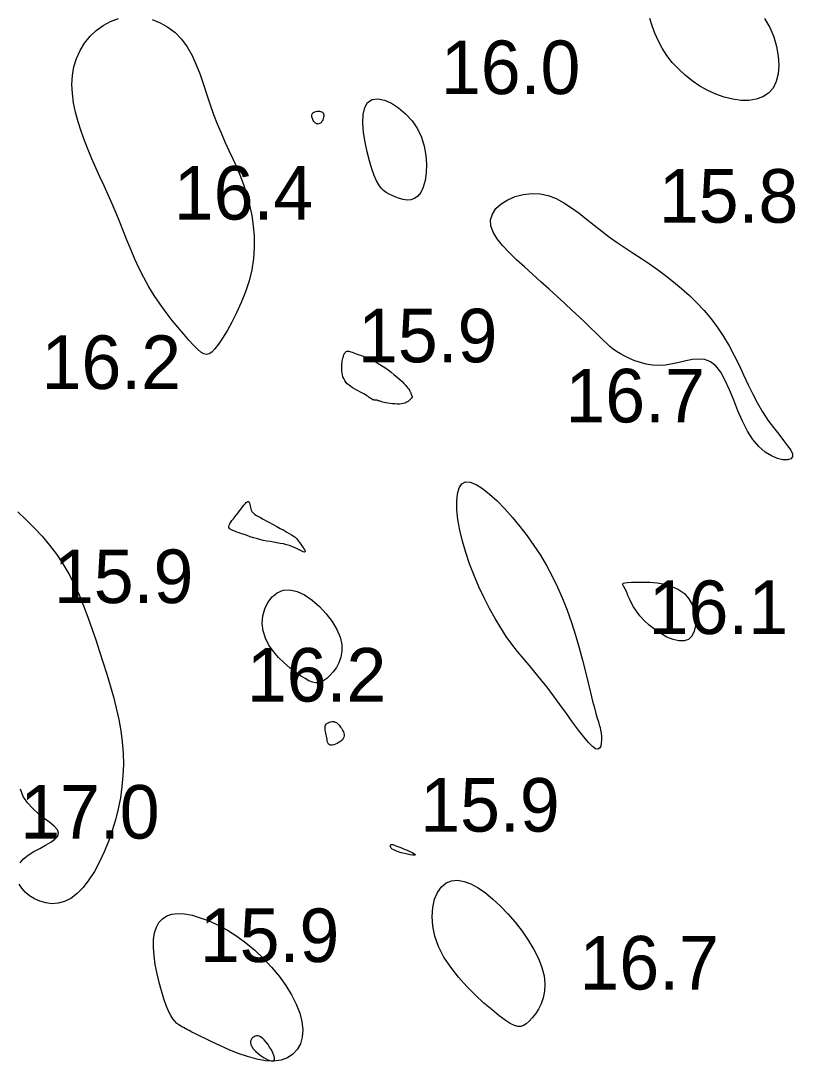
# Model space of a CAD drawing. Extents: x 3040093 to 3056816, y 408076 to 509144.
# Drawn here: x 3045686.6 to 3045758.8, y 434161.7 to 434258.8 of the extents above; entities that cross this region are included whole.
import ezdxf

# ---------------------------------------------------------------- set-up
doc = ezdxf.new("R2010")
doc.units = 0
doc.layers.add('V-CHAN-CONT-EL17', color=7, linetype='Continuous')
doc.layers.add('V-TOPO-SOUN-0610', color=7, linetype='Continuous')

msp = doc.modelspace()

# ---------------------------------------------------------------- linework, layer by layer
at = {"layer": 'V-CHAN-CONT-EL17'}
for points in [[(3045698.81, 434258.889), (3045699.574, 434258.588), (3045700.298, 434258.179), (3045700.969, 434257.665), (3045701.571, 434257.048), (3045702.094, 434256.332), (3045702.547, 434255.534), (3045702.944, 434254.671), (3045703.298, 434253.762), (3045703.622, 434252.824), (3045703.93, 434251.876), (3045704.236, 434250.936), (3045704.553, 434250.021), (3045704.891, 434249.146), (3045705.247, 434248.304), (3045705.614, 434247.486), (3045705.985, 434246.682), (3045706.354, 434245.879), (3045706.713, 434245.07), (3045707.055, 434244.242), (3045707.374, 434243.387), (3045707.662, 434242.495), (3045707.912, 434241.57), (3045708.115, 434240.614), (3045708.262, 434239.633), (3045708.344, 434238.631), (3045708.354, 434237.611), (3045708.282, 434236.579), (3045708.12, 434235.539), (3045707.865, 434234.497), (3045707.531, 434233.469), (3045707.139, 434232.472), (3045706.708, 434231.525), (3045706.259, 434230.646), (3045705.811, 434229.851), (3045705.385, 434229.16), (3045705, 434228.59), (3045704.671, 434228.155), (3045704.387, 434227.853), (3045704.13, 434227.678), (3045703.886, 434227.624), (3045703.636, 434227.686), (3045703.365, 434227.858), (3045703.055, 434228.133), (3045702.691, 434228.506), (3045702.26, 434228.97), (3045701.772, 434229.517), (3045701.243, 434230.135), (3045700.688, 434230.816), (3045700.121, 434231.549), (3045699.558, 434232.323), (3045699.013, 434233.13), (3045698.502, 434233.959), (3045698.037, 434234.802), (3045697.611, 434235.654), (3045697.219, 434236.513), (3045696.85, 434237.377), (3045696.498, 434238.242), (3045696.155, 434239.107), (3045695.811, 434239.97), (3045695.459, 434240.826), (3045695.094, 434241.675), (3045694.717, 434242.519), (3045694.334, 434243.36), (3045693.95, 434244.2), (3045693.57, 434245.042), (3045693.199, 434245.888), (3045692.841, 434246.741), (3045692.502, 434247.604), (3045692.188, 434248.477), (3045691.907, 434249.356), (3045691.671, 434250.238), (3045691.489, 434251.115), (3045691.372, 434251.984), (3045691.33, 434252.839), (3045691.373, 434253.674), (3045691.512, 434254.486), (3045691.753, 434255.267), (3045692.091, 434256.007), (3045692.517, 434256.696), (3045693.023, 434257.322), (3045693.6, 434257.875), (3045694.238, 434258.343), (3045694.929, 434258.714), (3045695.665, 434258.979)], [(3045755.981, 434258.975), (3045756.455, 434258.147), (3045756.829, 434257.27), (3045757.099, 434256.371), (3045757.261, 434255.478), (3045757.313, 434254.615), (3045757.251, 434253.812), (3045757.071, 434253.093), (3045756.771, 434252.486), (3045756.349, 434252.012), (3045755.821, 434251.669), (3045755.205, 434251.448), (3045754.519, 434251.343), (3045753.78, 434251.344), (3045753.008, 434251.445), (3045752.22, 434251.636), (3045751.435, 434251.911), (3045750.668, 434252.261), (3045749.927, 434252.68), (3045749.22, 434253.16), (3045748.553, 434253.693), (3045747.932, 434254.274), (3045747.364, 434254.894), (3045746.856, 434255.547), (3045746.413, 434256.225), (3045746.039, 434256.92), (3045745.731, 434257.619), (3045745.48, 434258.308), (3045745.279, 434258.972)], [(3045686.295, 434212.938), (3045687.065, 434212.209), (3045687.816, 434211.453), (3045688.543, 434210.667), (3045689.237, 434209.849), (3045689.889, 434208.994), (3045690.493, 434208.101), (3045691.044, 434207.167), (3045691.544, 434206.196), (3045692.003, 434205.195), (3045692.426, 434204.168), (3045692.82, 434203.122), (3045693.192, 434202.063), (3045693.55, 434200.996), (3045693.899, 434199.927), (3045694.246, 434198.86), (3045694.584, 434197.797), (3045694.906, 434196.737), (3045695.206, 434195.68), (3045695.476, 434194.626), (3045695.709, 434193.573), (3045695.897, 434192.523), (3045696.033, 434191.475), (3045696.112, 434190.428), (3045696.133, 434189.383), (3045696.097, 434188.342), (3045696.005, 434187.303), (3045695.859, 434186.269), (3045695.659, 434185.24), (3045695.407, 434184.217), (3045695.104, 434183.199), (3045694.751, 434182.192), (3045694.353, 434181.21), (3045693.913, 434180.272), (3045693.436, 434179.396), (3045692.927, 434178.599), (3045692.389, 434177.902), (3045691.828, 434177.32), (3045691.247, 434176.874), (3045690.653, 434176.576), (3045690.054, 434176.415), (3045689.461, 434176.376), (3045688.886, 434176.443), (3045688.339, 434176.6), (3045687.831, 434176.832), (3045687.373, 434177.123), (3045686.975, 434177.457), (3045686.647, 434177.821), (3045686.396, 434178.205)], [(3045686.496, 434180.203), (3045686.826, 434180.572), (3045687.265, 434180.915), (3045687.78, 434181.238), (3045688.327, 434181.543), (3045688.866, 434181.837), (3045689.354, 434182.122), (3045689.749, 434182.406), (3045690.009, 434182.69), (3045690.093, 434182.982), (3045689.973, 434183.285), (3045689.68, 434183.608), (3045689.258, 434183.957), (3045688.752, 434184.342), (3045688.208, 434184.771), (3045687.67, 434185.25), (3045687.183, 434185.789), (3045686.792, 434186.395), (3045686.53, 434187.074)]]:
    msp.add_lwpolyline(points, dxfattribs=at)
for points in [[(3045719.343, 434251.423), (3045719.876, 434251.485), (3045720.491, 434251.363), (3045721.153, 434251.078), (3045721.828, 434250.649), (3045722.48, 434250.096), (3045723.073, 434249.439), (3045723.574, 434248.7), (3045723.954, 434247.897), (3045724.215, 434247.058), (3045724.369, 434246.209), (3045724.426, 434245.377), (3045724.396, 434244.589), (3045724.29, 434243.871), (3045724.117, 434243.25), (3045723.888, 434242.753), (3045723.614, 434242.399), (3045723.303, 434242.176), (3045722.967, 434242.063), (3045722.614, 434242.041), (3045722.254, 434242.09), (3045721.896, 434242.19), (3045721.551, 434242.321), (3045721.228, 434242.462), (3045720.934, 434242.601), (3045720.666, 434242.75), (3045720.419, 434242.928), (3045720.189, 434243.155), (3045719.968, 434243.451), (3045719.753, 434243.834), (3045719.538, 434244.325), (3045719.318, 434244.942), (3045719.092, 434245.693), (3045718.875, 434246.545), (3045718.689, 434247.45), (3045718.554, 434248.361), (3045718.49, 434249.234), (3045718.517, 434250.022), (3045718.656, 434250.678), (3045718.928, 434251.157)], [(3045713.713, 434249.89), (3045713.717, 434249.965), (3045713.734, 434250.034), (3045713.763, 434250.098), (3045713.805, 434250.155), (3045713.86, 434250.205), (3045713.928, 434250.249), (3045714.01, 434250.285), (3045714.106, 434250.313), (3045714.21, 434250.332), (3045714.32, 434250.34), (3045714.429, 434250.337), (3045714.533, 434250.319), (3045714.629, 434250.287), (3045714.71, 434250.239), (3045714.772, 434250.173), (3045714.813, 434250.089), (3045714.832, 434249.99), (3045714.833, 434249.881), (3045714.818, 434249.767), (3045714.789, 434249.652), (3045714.748, 434249.54), (3045714.699, 434249.436), (3045714.643, 434249.346), (3045714.582, 434249.271), (3045714.518, 434249.213), (3045714.452, 434249.172), (3045714.383, 434249.147), (3045714.313, 434249.138), (3045714.242, 434249.144), (3045714.172, 434249.166), (3045714.103, 434249.202), (3045714.036, 434249.252), (3045713.972, 434249.315), (3045713.912, 434249.387), (3045713.858, 434249.467), (3045713.81, 434249.551), (3045713.771, 434249.638), (3045713.741, 434249.725), (3045713.721, 434249.81)], [(3045733.557, 434235.801), (3045732.818, 434236.477), (3045732.134, 434237.14), (3045731.529, 434237.788), (3045731.029, 434238.42), (3045730.659, 434239.033), (3045730.444, 434239.625), (3045730.41, 434240.195), (3045730.573, 434240.738), (3045730.912, 434241.242), (3045731.399, 434241.692), (3045732.003, 434242.074), (3045732.697, 434242.373), (3045733.451, 434242.575), (3045734.235, 434242.666), (3045735.021, 434242.631), (3045735.784, 434242.462), (3045736.525, 434242.173), (3045737.248, 434241.786), (3045737.959, 434241.323), (3045738.662, 434240.804), (3045739.363, 434240.25), (3045740.067, 434239.684), (3045740.778, 434239.126), (3045741.501, 434238.593), (3045742.235, 434238.081), (3045742.977, 434237.582), (3045743.726, 434237.089), (3045744.479, 434236.593), (3045745.235, 434236.086), (3045745.99, 434235.561), (3045746.744, 434235.008), (3045747.493, 434234.422), (3045748.233, 434233.801), (3045748.957, 434233.144), (3045749.66, 434232.451), (3045750.337, 434231.723), (3045750.981, 434230.958), (3045751.587, 434230.156), (3045752.149, 434229.318), (3045752.665, 434228.445), (3045753.143, 434227.546), (3045753.592, 434226.633), (3045754.025, 434225.718), (3045754.45, 434224.812), (3045754.881, 434223.927), (3045755.326, 434223.074), (3045755.796, 434222.266), (3045756.297, 434221.512), (3045756.808, 434220.817), (3045757.302, 434220.185), (3045757.752, 434219.618), (3045758.131, 434219.121), (3045758.414, 434218.696), (3045758.573, 434218.347), (3045758.582, 434218.078), (3045758.423, 434217.892), (3045758.118, 434217.798), (3045757.695, 434217.805), (3045757.185, 434217.923), (3045756.618, 434218.161), (3045756.024, 434218.529), (3045755.433, 434219.034), (3045754.874, 434219.688), (3045754.371, 434220.489), (3045753.917, 434221.401), (3045753.498, 434222.376), (3045753.1, 434223.367), (3045752.709, 434224.328), (3045752.312, 434225.212), (3045751.894, 434225.971), (3045751.443, 434226.56), (3045750.946, 434226.945), (3045750.41, 434227.149), (3045749.839, 434227.209), (3045749.243, 434227.162), (3045748.628, 434227.045), (3045748.001, 434226.895), (3045747.37, 434226.749), (3045746.743, 434226.644), (3045746.125, 434226.609), (3045745.523, 434226.642), (3045744.942, 434226.732), (3045744.386, 434226.87), (3045743.861, 434227.044), (3045743.372, 434227.245), (3045742.925, 434227.463), (3045742.523, 434227.687), (3045742.169, 434227.91), (3045741.85, 434228.138), (3045741.55, 434228.379), (3045741.253, 434228.642), (3045740.943, 434228.935), (3045740.604, 434229.268), (3045740.22, 434229.648), (3045739.775, 434230.084), (3045739.257, 434230.583), (3045738.673, 434231.137), (3045738.031, 434231.737), (3045737.343, 434232.375), (3045736.618, 434233.041), (3045735.866, 434233.725), (3045735.098, 434234.419), (3045734.324, 434235.114)], [(3045719.723, 434223.374), (3045719.677, 434223.377), (3045719.63, 434223.377), (3045719.583, 434223.378), (3045719.535, 434223.382), (3045719.484, 434223.39), (3045719.43, 434223.405), (3045719.373, 434223.43), (3045719.312, 434223.465), (3045719.245, 434223.511), (3045719.169, 434223.566), (3045719.082, 434223.63), (3045718.981, 434223.703), (3045718.864, 434223.782), (3045718.729, 434223.868), (3045718.573, 434223.959), (3045718.396, 434224.055), (3045718.201, 434224.157), (3045717.996, 434224.264), (3045717.787, 434224.377), (3045717.58, 434224.497), (3045717.382, 434224.625), (3045717.198, 434224.76), (3045717.036, 434224.904), (3045716.9, 434225.056), (3045716.789, 434225.215), (3045716.7, 434225.38), (3045716.632, 434225.549), (3045716.582, 434225.72), (3045716.548, 434225.892), (3045716.526, 434226.062), (3045716.516, 434226.229), (3045716.514, 434226.393), (3045716.519, 434226.551), (3045716.53, 434226.704), (3045716.547, 434226.851), (3045716.569, 434226.992), (3045716.594, 434227.126), (3045716.622, 434227.253), (3045716.652, 434227.372), (3045716.683, 434227.483), (3045716.715, 434227.586), (3045716.751, 434227.678), (3045716.79, 434227.758), (3045716.835, 434227.826), (3045716.885, 434227.881), (3045716.942, 434227.92), (3045717.007, 434227.944), (3045717.081, 434227.951), (3045717.166, 434227.942), (3045717.261, 434227.92), (3045717.37, 434227.886), (3045717.493, 434227.842), (3045717.631, 434227.789), (3045717.786, 434227.729), (3045717.959, 434227.664), (3045718.15, 434227.595), (3045718.36, 434227.521), (3045718.586, 434227.437), (3045718.828, 434227.343), (3045719.084, 434227.235), (3045719.354, 434227.111), (3045719.636, 434226.968), (3045719.928, 434226.804), (3045720.229, 434226.617), (3045720.535, 434226.413), (3045720.839, 434226.195), (3045721.136, 434225.97), (3045721.42, 434225.744), (3045721.687, 434225.521), (3045721.93, 434225.308), (3045722.143, 434225.109), (3045722.324, 434224.93), (3045722.474, 434224.769), (3045722.596, 434224.627), (3045722.693, 434224.502), (3045722.77, 434224.393), (3045722.828, 434224.3), (3045722.873, 434224.22), (3045722.906, 434224.153), (3045722.932, 434224.099), (3045722.952, 434224.054), (3045722.966, 434224.018), (3045722.977, 434223.988), (3045722.986, 434223.962), (3045722.993, 434223.939), (3045723, 434223.917), (3045723.009, 434223.893), (3045723.02, 434223.868), (3045723.033, 434223.839), (3045723.047, 434223.809), (3045723.06, 434223.779), (3045723.072, 434223.748), (3045723.082, 434223.718), (3045723.088, 434223.689), (3045723.09, 434223.663), (3045723.087, 434223.638), (3045723.078, 434223.616), (3045723.063, 434223.593), (3045723.043, 434223.568), (3045723.016, 434223.541), (3045722.984, 434223.51), (3045722.944, 434223.472), (3045722.898, 434223.428), (3045722.845, 434223.376), (3045722.783, 434223.318), (3045722.709, 434223.258), (3045722.622, 434223.197), (3045722.519, 434223.14), (3045722.398, 434223.09), (3045722.257, 434223.048), (3045722.093, 434223.019), (3045721.906, 434223.004), (3045721.701, 434223.003), (3045721.485, 434223.012), (3045721.263, 434223.031), (3045721.044, 434223.057), (3045720.832, 434223.089), (3045720.636, 434223.123), (3045720.46, 434223.159), (3045720.311, 434223.195), (3045720.187, 434223.229), (3045720.084, 434223.261), (3045719.999, 434223.291), (3045719.928, 434223.317), (3045719.869, 434223.339), (3045719.817, 434223.356), (3045719.769, 434223.368)], [(3045735.107, 434197.303), (3045734.544, 434197.985), (3045733.995, 434198.637), (3045733.456, 434199.279), (3045732.925, 434199.928), (3045732.399, 434200.605), (3045731.875, 434201.328), (3045731.351, 434202.115), (3045730.825, 434202.981), (3045730.305, 434203.917), (3045729.799, 434204.909), (3045729.315, 434205.942), (3045728.863, 434207.004), (3045728.45, 434208.08), (3045728.085, 434209.156), (3045727.776, 434210.218), (3045727.533, 434211.25), (3045727.359, 434212.232), (3045727.261, 434213.139), (3045727.242, 434213.949), (3045727.308, 434214.637), (3045727.464, 434215.18), (3045727.715, 434215.556), (3045728.065, 434215.74), (3045728.515, 434215.718), (3045729.053, 434215.505), (3045729.661, 434215.126), (3045730.321, 434214.605), (3045731.017, 434213.966), (3045731.731, 434213.234), (3045732.447, 434212.433), (3045733.147, 434211.587), (3045733.816, 434210.715), (3045734.452, 434209.82), (3045735.054, 434208.898), (3045735.624, 434207.944), (3045736.16, 434206.957), (3045736.663, 434205.932), (3045737.132, 434204.867), (3045737.568, 434203.757), (3045737.971, 434202.605), (3045738.341, 434201.43), (3045738.679, 434200.257), (3045738.987, 434199.111), (3045739.265, 434198.016), (3045739.515, 434196.998), (3045739.736, 434196.081), (3045739.931, 434195.29), (3045740.099, 434194.642), (3045740.243, 434194.12), (3045740.366, 434193.7), (3045740.468, 434193.358), (3045740.552, 434193.07), (3045740.62, 434192.812), (3045740.674, 434192.559), (3045740.716, 434192.287), (3045740.746, 434191.98), (3045740.757, 434191.659), (3045740.739, 434191.352), (3045740.684, 434191.088), (3045740.583, 434190.896), (3045740.427, 434190.805), (3045740.206, 434190.842), (3045739.912, 434191.038), (3045739.539, 434191.41), (3045739.097, 434191.937), (3045738.597, 434192.587), (3045738.053, 434193.328), (3045737.477, 434194.13), (3045736.882, 434194.959), (3045736.281, 434195.784), (3045735.686, 434196.573)], [(3045711.362, 434209.875), (3045711.068, 434209.946), (3045710.766, 434210.006), (3045710.458, 434210.06), (3045710.145, 434210.111), (3045709.829, 434210.163), (3045709.511, 434210.22), (3045709.194, 434210.284), (3045708.88, 434210.359), (3045708.57, 434210.444), (3045708.267, 434210.534), (3045707.972, 434210.628), (3045707.69, 434210.724), (3045707.42, 434210.817), (3045707.167, 434210.907), (3045706.932, 434210.989), (3045706.717, 434211.063), (3045706.525, 434211.131), (3045706.358, 434211.196), (3045706.219, 434211.261), (3045706.108, 434211.33), (3045706.03, 434211.406), (3045705.986, 434211.492), (3045705.978, 434211.592), (3045706.007, 434211.708), (3045706.069, 434211.839), (3045706.159, 434211.983), (3045706.272, 434212.139), (3045706.402, 434212.306), (3045706.544, 434212.481), (3045706.692, 434212.663), (3045706.841, 434212.851), (3045706.987, 434213.042), (3045707.126, 434213.229), (3045707.259, 434213.407), (3045707.382, 434213.569), (3045707.496, 434213.708), (3045707.597, 434213.817), (3045707.685, 434213.889), (3045707.758, 434213.919), (3045707.816, 434213.901), (3045707.861, 434213.842), (3045707.897, 434213.75), (3045707.928, 434213.633), (3045707.957, 434213.502), (3045707.987, 434213.363), (3045708.024, 434213.225), (3045708.07, 434213.097), (3045708.129, 434212.986), (3045708.204, 434212.887), (3045708.299, 434212.797), (3045708.417, 434212.708), (3045708.562, 434212.617), (3045708.737, 434212.518), (3045708.946, 434212.406), (3045709.192, 434212.275), (3045709.476, 434212.121), (3045709.788, 434211.95), (3045710.118, 434211.768), (3045710.454, 434211.582), (3045710.784, 434211.398), (3045711.097, 434211.222), (3045711.381, 434211.061), (3045711.624, 434210.921), (3045711.819, 434210.808), (3045711.971, 434210.716), (3045712.088, 434210.638), (3045712.181, 434210.567), (3045712.257, 434210.498), (3045712.326, 434210.422), (3045712.397, 434210.333), (3045712.479, 434210.224), (3045712.577, 434210.091), (3045712.686, 434209.94), (3045712.798, 434209.782), (3045712.903, 434209.625), (3045712.993, 434209.479), (3045713.059, 434209.354), (3045713.093, 434209.259), (3045713.085, 434209.202), (3045713.03, 434209.192), (3045712.929, 434209.222), (3045712.788, 434209.285), (3045712.612, 434209.371), (3045712.405, 434209.473), (3045712.171, 434209.582), (3045711.916, 434209.691), (3045711.645, 434209.791)], [(3045709.102, 434202.534), (3045709.16, 434203.23), (3045709.34, 434203.893), (3045709.631, 434204.494), (3045710.022, 434205.003), (3045710.501, 434205.388), (3045711.056, 434205.622), (3045711.678, 434205.672), (3045712.352, 434205.52), (3045713.054, 434205.188), (3045713.757, 434204.708), (3045714.435, 434204.114), (3045715.06, 434203.439), (3045715.607, 434202.716), (3045716.047, 434201.976), (3045716.354, 434201.254), (3045716.511, 434200.576), (3045716.531, 434199.95), (3045716.44, 434199.379), (3045716.259, 434198.863), (3045716.013, 434198.406), (3045715.725, 434198.008), (3045715.419, 434197.673), (3045715.118, 434197.403), (3045714.84, 434197.198), (3045714.579, 434197.06), (3045714.322, 434196.989), (3045714.057, 434196.985), (3045713.773, 434197.048), (3045713.457, 434197.18), (3045713.097, 434197.38), (3045712.681, 434197.648), (3045712.203, 434197.984), (3045711.683, 434198.384), (3045711.148, 434198.843), (3045710.625, 434199.355), (3045710.139, 434199.916), (3045709.718, 434200.519), (3045709.388, 434201.161), (3045709.176, 434201.836)], [(3045748.924, 434204.814), (3045749.238, 434204.232), (3045749.442, 434203.603), (3045749.536, 434202.965), (3045749.524, 434202.353), (3045749.408, 434201.805), (3045749.19, 434201.357), (3045748.872, 434201.045), (3045748.461, 434200.895), (3045747.975, 434200.897), (3045747.437, 434201.026), (3045746.868, 434201.262), (3045746.29, 434201.581), (3045745.727, 434201.962), (3045745.2, 434202.382), (3045744.731, 434202.819), (3045744.338, 434203.254), (3045744.015, 434203.678), (3045743.753, 434204.085), (3045743.541, 434204.471), (3045743.369, 434204.829), (3045743.229, 434205.154), (3045743.108, 434205.44), (3045742.998, 434205.681), (3045742.893, 434205.875), (3045742.805, 434206.025), (3045742.75, 434206.138), (3045742.745, 434206.22), (3045742.806, 434206.277), (3045742.949, 434206.317), (3045743.192, 434206.346), (3045743.55, 434206.369), (3045744.031, 434206.39), (3045744.614, 434206.398), (3045745.267, 434206.377), (3045745.959, 434206.312), (3045746.659, 434206.188), (3045747.335, 434205.991), (3045747.958, 434205.705), (3045748.496, 434205.315)], [(3045715.372, 434191.19), (3045715.293, 434191.251), (3045715.235, 434191.338), (3045715.193, 434191.446), (3045715.163, 434191.571), (3045715.14, 434191.708), (3045715.119, 434191.853), (3045715.095, 434192.002), (3045715.066, 434192.149), (3045715.033, 434192.293), (3045715.002, 434192.434), (3045714.976, 434192.569), (3045714.958, 434192.698), (3045714.954, 434192.82), (3045714.967, 434192.932), (3045715.002, 434193.034), (3045715.06, 434193.125), (3045715.139, 434193.204), (3045715.235, 434193.269), (3045715.343, 434193.32), (3045715.459, 434193.357), (3045715.578, 434193.377), (3045715.697, 434193.38), (3045715.81, 434193.365), (3045715.914, 434193.332), (3045716.011, 434193.283), (3045716.099, 434193.218), (3045716.183, 434193.141), (3045716.261, 434193.053), (3045716.336, 434192.956), (3045716.409, 434192.853), (3045716.482, 434192.745), (3045716.554, 434192.634), (3045716.621, 434192.52), (3045716.679, 434192.404), (3045716.722, 434192.286), (3045716.747, 434192.166), (3045716.746, 434192.045), (3045716.717, 434191.922), (3045716.653, 434191.798), (3045716.552, 434191.674), (3045716.421, 434191.554), (3045716.268, 434191.441), (3045716.101, 434191.342), (3045715.93, 434191.259), (3045715.763, 434191.199), (3045715.609, 434191.164), (3045715.477, 434191.16)], [(3045721.367, 434181.39), (3045721.231, 434181.476), (3045721.139, 434181.559), (3045721.084, 434181.637), (3045721.059, 434181.709), (3045721.057, 434181.772), (3045721.073, 434181.826), (3045721.098, 434181.867), (3045721.129, 434181.895), (3045721.169, 434181.909), (3045721.222, 434181.909), (3045721.293, 434181.894), (3045721.387, 434181.863), (3045721.509, 434181.817), (3045721.665, 434181.754), (3045721.858, 434181.675), (3045722.09, 434181.58), (3045722.346, 434181.474), (3045722.609, 434181.362), (3045722.86, 434181.251), (3045723.08, 434181.147), (3045723.252, 434181.055), (3045723.358, 434180.982), (3045723.378, 434180.933), (3045723.301, 434180.912), (3045723.141, 434180.918), (3045722.917, 434180.947), (3045722.651, 434180.995), (3045722.361, 434181.058), (3045722.068, 434181.133), (3045721.792, 434181.215), (3045721.553, 434181.302)], [(3045725.2, 434173.337), (3045725.002, 434174.285), (3045724.942, 434175.19), (3045725.007, 434176.032), (3045725.184, 434176.788), (3045725.462, 434177.436), (3045725.826, 434177.956), (3045726.266, 434178.324), (3045726.769, 434178.526), (3045727.326, 434178.568), (3045727.928, 434178.462), (3045728.567, 434178.221), (3045729.235, 434177.857), (3045729.923, 434177.383), (3045730.623, 434176.812), (3045731.326, 434176.155), (3045732.024, 434175.426), (3045732.7, 434174.64), (3045733.339, 434173.814), (3045733.924, 434172.963), (3045734.439, 434172.103), (3045734.869, 434171.251), (3045735.196, 434170.423), (3045735.405, 434169.634), (3045735.485, 434168.898), (3045735.451, 434168.219), (3045735.324, 434167.599), (3045735.123, 434167.038), (3045734.87, 434166.538), (3045734.586, 434166.1), (3045734.29, 434165.726), (3045734.004, 434165.417), (3045733.741, 434165.175), (3045733.489, 434165.007), (3045733.232, 434164.919), (3045732.949, 434164.918), (3045732.624, 434165.011), (3045732.238, 434165.206), (3045731.773, 434165.508), (3045731.211, 434165.926), (3045730.542, 434166.463), (3045729.792, 434167.106), (3045728.997, 434167.842), (3045728.19, 434168.654), (3045727.407, 434169.528), (3045726.683, 434170.448), (3045726.051, 434171.4), (3045725.548, 434172.368)], [(3045699.046, 434173.652), (3045699.213, 434174.189), (3045699.459, 434174.632), (3045699.783, 434174.98), (3045700.185, 434175.233), (3045700.663, 434175.391), (3045701.218, 434175.454), (3045701.849, 434175.421), (3045702.553, 434175.293), (3045703.318, 434175.072), (3045704.131, 434174.764), (3045704.978, 434174.37), (3045705.844, 434173.896), (3045706.715, 434173.345), (3045707.577, 434172.721), (3045708.417, 434172.027), (3045709.221, 434171.27), (3045709.975, 434170.462), (3045710.669, 434169.618), (3045711.289, 434168.753), (3045711.825, 434167.881), (3045712.263, 434167.016), (3045712.591, 434166.174), (3045712.798, 434165.369), (3045712.874, 434164.615), (3045712.823, 434163.924), (3045712.651, 434163.305), (3045712.363, 434162.77), (3045711.966, 434162.33), (3045711.466, 434161.994), (3045710.87, 434161.774), (3045710.183, 434161.68), (3045709.414, 434161.717), (3045708.587, 434161.866), (3045707.727, 434162.104), (3045706.859, 434162.405), (3045706.009, 434162.746), (3045705.203, 434163.102), (3045704.466, 434163.449), (3045703.824, 434163.762), (3045703.296, 434164.023), (3045702.871, 434164.234), (3045702.535, 434164.402), (3045702.27, 434164.537), (3045702.061, 434164.645), (3045701.891, 434164.734), (3045701.744, 434164.813), (3045701.603, 434164.888), (3045701.456, 434164.97), (3045701.299, 434165.07), (3045701.132, 434165.204), (3045700.954, 434165.386), (3045700.767, 434165.631), (3045700.569, 434165.951), (3045700.361, 434166.363), (3045700.141, 434166.88), (3045699.913, 434167.509), (3045699.685, 434168.231), (3045699.469, 434169.019), (3045699.275, 434169.847), (3045699.116, 434170.688), (3045699.003, 434171.515), (3045698.946, 434172.302), (3045698.957, 434173.022)], [(3045710.236, 434161.81), (3045710.239, 434161.978), (3045710.183, 434162.198), (3045710.082, 434162.452), (3045709.945, 434162.725), (3045709.784, 434163.001), (3045709.611, 434163.263), (3045709.436, 434163.494), (3045709.269, 434163.683), (3045709.111, 434163.829), (3045708.963, 434163.934), (3045708.822, 434164.002), (3045708.69, 434164.036), (3045708.564, 434164.04), (3045708.445, 434164.015), (3045708.332, 434163.965), (3045708.226, 434163.894), (3045708.132, 434163.801), (3045708.059, 434163.688), (3045708.013, 434163.555), (3045708.003, 434163.404), (3045708.036, 434163.234), (3045708.119, 434163.048), (3045708.259, 434162.844), (3045708.46, 434162.627), (3045708.709, 434162.406), (3045708.985, 434162.195), (3045709.273, 434162.005), (3045709.553, 434161.849), (3045709.806, 434161.74), (3045710.016, 434161.689), (3045710.164, 434161.71)]]:
    msp.add_lwpolyline(points, close=True, dxfattribs=at)

# ---------------------------------------------------------------- texts
at = {"layer": 'V-TOPO-SOUN-0610'}
for s, p in [('16.0 ', (3045725.773, 434251.93)), ('16.4 ', (3045700.843, 434240.22)), ('15.8 ', (3045746.113, 434239.93)), ('15.9 ', (3045718.033, 434226.9)), ('16.2 ', (3045688.503, 434224.41)), ('16.7 ', (3045737.393, 434221.29)), ('15.9 ', (3045689.653, 434204.43)), ('16.1 ', (3045745.163, 434201.54)), ('16.2 ', (3045707.663, 434195.24)), ('17.0 ', (3045686.503, 434182.45)), ('15.9 ', (3045723.843, 434183.1)), ('15.9 ', (3045703.273, 434170.93)), ('16.7 ', (3045738.703, 434168.37))]:
    msp.add_text(s, height=5, dxfattribs=at).set_placement(p)

doc.saveas('drawing.dxf')
